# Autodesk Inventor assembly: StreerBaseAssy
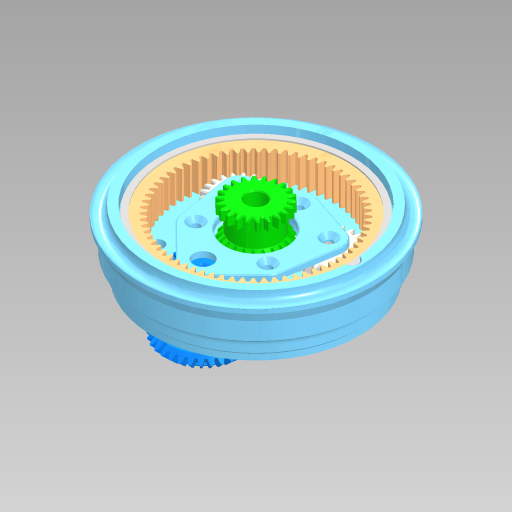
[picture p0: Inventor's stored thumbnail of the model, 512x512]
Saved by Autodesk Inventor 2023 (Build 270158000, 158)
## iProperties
Created: 2024-05
Part Number: StreerBaseAssy
Document SubType Name: Assembly
Designer: kumagai
Author: kumagai
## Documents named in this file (9)
- X:\Develop\CAD\NakataOmni\DriveUnitR3\StreerBaseAssy.iam
- X:\Develop\CAD\NakataOmni\DriveUnitR3\SteerBase.ipt
- X:\Develop\CAD\NakataOmni\DriveUnitR3\CarrierPlate.ipt
- X:\Develop\CAD\NakataOmni\DriveUnitR3\PlanetaryGear_idle.ipt
- X:\Develop\CAD\NakataOmni\DriveUnitR3\PlanetaryGear_Output.ipt
- X:\Develop\CAD\NakataOmni\DriveUnitR3\InternalGear_C.ipt
- X:\Develop\CAD\NakataOmni\DriveUnitR3\Ratainer_IG_SB.ipt
- X:\Develop\CAD\NakataOmni\DriveUnitR3\SunGear_conn.ipt
- X:\Develop\CAD\NakataOmni\DriveUnitR3\BevelGear_32_H.ipt
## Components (9 placed, 6 different names)
1. SteerBase:1 — メイト:1, メイト:2, メイト:3, メイト:4, メイト:5, メイト:6, メイト:7, メイト:8, フラッシュ:1, メイト:9, メイト:10, メイト:11, メイト:13, メイト:14, メイト:16
2. CarrierPlate:1 — メイト:7, メイト:8, フラッシュ:1
3. 平歯車1:1 — メイト:2, メイト:5
4. 平歯車1:2 — メイト:1, メイト:4
5. 平歯車1:3 — メイト:3, メイト:6, フラッシュ:2, メイト:15
6. InternalGear_C:1 — メイト:9, メイト:10, メイト:12
7. Ratainer_IG_SB:1 — メイト:11, メイト:12
8. 平歯車1:4 — メイト:13, メイト:14
9. かさ歯車1:1 — フラッシュ:2, メイト:15, メイト:16
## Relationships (18: Mate 16, Flush 2)
- メイト:1 [Mate]: SteerBase:1 ↔ 平歯車1:2
- メイト:2 [Mate]: SteerBase:1 ↔ 平歯車1:1
- メイト:3 [Mate]: SteerBase:1 ↔ 平歯車1:3
- メイト:4 [Mate]: SteerBase:1 ↔ 平歯車1:2
- メイト:5 [Mate]: SteerBase:1 ↔ 平歯車1:1
- メイト:6 [Mate]: SteerBase:1 ↔ 平歯車1:3
- メイト:7 [Mate]: SteerBase:1 ↔ CarrierPlate:1
- メイト:8 [Mate]: SteerBase:1 ↔ CarrierPlate:1
- フラッシュ:1 [Flush]: SteerBase:1 ↔ CarrierPlate:1
- メイト:9 [Mate]: SteerBase:1 ↔ InternalGear_C:1
- メイト:10 [Mate]: SteerBase:1 ↔ InternalGear_C:1
- メイト:11 [Mate]: SteerBase:1 ↔ Ratainer_IG_SB:1
- メイト:12 [Mate]: InternalGear_C:1 ↔ Ratainer_IG_SB:1
- メイト:13 [Mate]: SteerBase:1 ↔ 平歯車1:4
- メイト:14 [Mate]: SteerBase:1 ↔ 平歯車1:4
- フラッシュ:2 [Flush]: 平歯車1:3 ↔ かさ歯車1:1
- メイト:15 [Mate]: 平歯車1:3 ↔ かさ歯車1:1
- メイト:16 [Mate]: SteerBase:1 ↔ かさ歯車1:1
